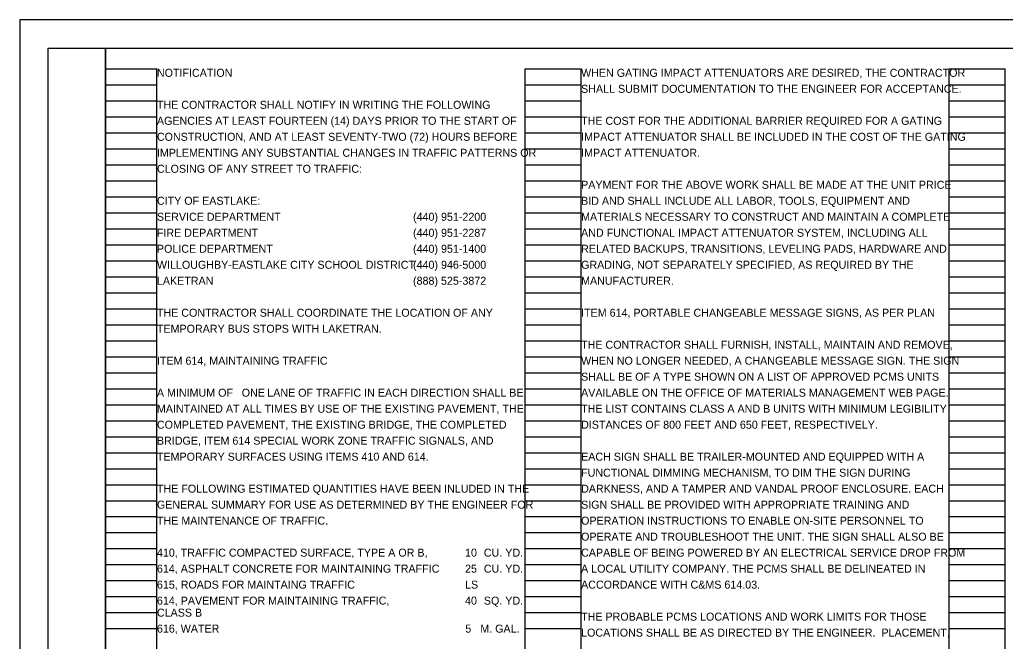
# Model space of a CAD drawing. Extents: x 0 to 34, y 0 to 22.
# Drawn here: x 0 to 17.24, y 11.12 to 22 of the extents above; entities that cross this region are included whole.
import ezdxf

# ---------------------------------------------------------------- set-up
doc = ezdxf.new("R2010")
doc.units = 0
for name, color, linetype in [('SH_Border', 7, 'Continuous'), ('SH_Cut_Line', 7, 'Continuous'), ('SH_Data', 7, 'Continuous'), ('SH_Text', 7, 'Continuous')]:
    doc.layers.add(name, color=color, linetype=linetype)

msp = doc.modelspace()

# ---------------------------------------------------------------- linework, layer by layer
at = {"layer": 'SH_Border'}
for points in [[(0.5, 21.5), (1.5, 21.5), (1.5, 0.5), (0.5, 0.5)], [(1.5, 21.5), (33.5, 21.5), (33.5, 0.5), (1.5, 0.5)]]:
    msp.add_lwpolyline(points, close=True, dxfattribs=at)
at = {"layer": 'SH_Cut_Line'}
msp.add_lwpolyline([(0, 0), (34, 0), (34, 22), (0, 22)], close=True, dxfattribs=at)
at = {"layer": 'SH_Data'}
for p, q in [((1.5, 0.98), (1.5, 21.14)), ((1.5, 21.14), (2.4, 21.14)), ((2.4, 0.98), (2.4, 21.14)), ((8.84, 0.98), (8.84, 21.14)), ((8.84, 21.14), (9.82, 21.14)), ((9.82, 0.98), (9.82, 21.14)), ((16.26, 0.98), (16.26, 21.14)), ((16.26, 21.14), (17.24, 21.14)), ((17.24, 0.98), (17.24, 21.14)), ((1.5, 20.86), (2.4, 20.86)), ((8.84, 20.86), (9.82, 20.86)), ((16.26, 20.86), (17.24, 20.86)), ((1.5, 20.58), (2.4, 20.58)), ((8.84, 20.58), (9.82, 20.58)), ((16.26, 20.58), (17.24, 20.58)), ((1.5, 20.3), (2.4, 20.3)), ((8.84, 20.3), (9.82, 20.3)), ((16.26, 20.3), (17.24, 20.3)), ((1.5, 20.02), (2.4, 20.02)), ((8.84, 20.02), (9.82, 20.02)), ((16.26, 20.02), (17.24, 20.02)), ((1.5, 19.74), (2.4, 19.74)), ((8.84, 19.74), (9.82, 19.74)), ((16.26, 19.74), (17.24, 19.74)), ((1.5, 19.46), (2.4, 19.46)), ((8.84, 19.46), (9.82, 19.46)), ((16.26, 19.46), (17.24, 19.46)), ((1.5, 19.18), (2.4, 19.18)), ((8.84, 19.18), (9.82, 19.18)), ((16.26, 19.18), (17.24, 19.18)), ((1.5, 18.9), (2.4, 18.9)), ((8.84, 18.9), (9.82, 18.9)), ((16.26, 18.9), (17.24, 18.9)), ((1.5, 18.62), (2.4, 18.62)), ((8.84, 18.62), (9.82, 18.62)), ((16.26, 18.62), (17.24, 18.62)), ((1.5, 18.34), (2.4, 18.34)), ((8.84, 18.34), (9.82, 18.34)), ((16.26, 18.34), (17.24, 18.34)), ((1.5, 18.06), (2.4, 18.06)), ((8.84, 18.06), (9.82, 18.06)), ((16.26, 18.06), (17.24, 18.06)), ((1.5, 17.78), (2.4, 17.78)), ((8.84, 17.78), (9.82, 17.78)), ((16.26, 17.78), (17.24, 17.78)), ((1.5, 17.5), (2.4, 17.5)), ((8.84, 17.5), (9.82, 17.5)), ((16.26, 17.5), (17.24, 17.5)), ((1.5, 17.22), (2.4, 17.22)), ((8.84, 17.22), (9.82, 17.22)), ((16.26, 17.22), (17.24, 17.22)), ((1.5, 16.94), (2.4, 16.94)), ((8.84, 16.94), (9.82, 16.94)), ((16.26, 16.94), (17.24, 16.94)), ((1.5, 16.66), (2.4, 16.66)), ((8.84, 16.66), (9.82, 16.66)), ((16.26, 16.66), (17.24, 16.66)), ((1.5, 16.38), (2.4, 16.38)), ((8.84, 16.38), (9.82, 16.38)), ((16.26, 16.38), (17.24, 16.38)), ((1.5, 16.1), (2.4, 16.1)), ((8.84, 16.1), (9.82, 16.1)), ((16.26, 16.1), (17.24, 16.1)), ((1.5, 15.82), (2.4, 15.82)), ((8.84, 15.82), (9.82, 15.82)), ((16.26, 15.82), (17.24, 15.82)), ((1.5, 15.54), (2.4, 15.54)), ((8.84, 15.54), (9.82, 15.54)), ((16.26, 15.54), (17.24, 15.54)), ((1.5, 15.26), (2.4, 15.26)), ((8.84, 15.26), (9.82, 15.26)), ((16.26, 15.26), (17.24, 15.26)), ((1.5, 14.98), (2.4, 14.98)), ((8.84, 14.98), (9.82, 14.98)), ((16.26, 14.98), (17.24, 14.98)), ((1.5, 14.7), (2.4, 14.7)), ((8.84, 14.7), (9.82, 14.7)), ((16.26, 14.7), (17.24, 14.7)), ((1.5, 14.42), (2.4, 14.42)), ((8.84, 14.42), (9.82, 14.42)), ((16.26, 14.42), (17.24, 14.42)), ((1.5, 14.14), (2.4, 14.14)), ((8.84, 14.14), (9.82, 14.14)), ((16.26, 14.14), (17.24, 14.14)), ((1.5, 13.86), (2.4, 13.86)), ((8.84, 13.86), (9.82, 13.86)), ((16.26, 13.86), (17.24, 13.86)), ((1.5, 13.58), (2.4, 13.58)), ((8.84, 13.58), (9.82, 13.58)), ((16.26, 13.58), (17.24, 13.58)), ((1.5, 13.3), (2.4, 13.3)), ((8.84, 13.3), (9.82, 13.3)), ((16.26, 13.3), (17.24, 13.3)), ((1.5, 13.02), (2.4, 13.02)), ((8.84, 13.02), (9.82, 13.02)), ((16.26, 13.02), (17.24, 13.02)), ((1.5, 12.74), (2.4, 12.74)), ((8.84, 12.74), (9.82, 12.74)), ((16.26, 12.74), (17.24, 12.74)), ((1.5, 12.46), (2.4, 12.46)), ((8.84, 12.46), (9.82, 12.46)), ((16.26, 12.46), (17.24, 12.46)), ((1.5, 12.18), (2.4, 12.18)), ((8.84, 12.18), (9.82, 12.18)), ((16.26, 12.18), (17.24, 12.18)), ((1.5, 11.9), (2.4, 11.9)), ((8.84, 11.9), (9.82, 11.9)), ((16.26, 11.9), (17.24, 11.9)), ((1.5, 11.62), (2.4, 11.62)), ((8.84, 11.62), (9.82, 11.62)), ((16.26, 11.62), (17.24, 11.62)), ((1.5, 11.34), (2.4, 11.34)), ((8.84, 11.34), (9.82, 11.34)), ((16.26, 11.34), (17.24, 11.34))]:
    msp.add_line(p, q, dxfattribs=at)

# ---------------------------------------------------------------- texts
at = {"layer": 'SH_Text'}
for s, p in [('NOTIFICATION', (2.4, 21)), ('WHEN GATING IMPACT ATTENUATORS ARE DESIRED, THE CONTRACTOR ', (9.82, 21)), ('SHALL SUBMIT DOCUMENTATION TO THE ENGINEER FOR ACCEPTANCE.', (9.82, 20.72)), ('THE CONTRACTOR SHALL NOTIFY IN WRITING THE FOLLOWING ', (2.4, 20.44)), ('AGENCIES AT LEAST FOURTEEN (14) DAYS PRIOR TO THE START OF ', (2.4, 20.16)), ('THE COST FOR THE ADDITIONAL BARRIER REQUIRED FOR A GATING ', (9.82, 20.16)), ('CONSTRUCTION, AND AT LEAST SEVENTY-TWO (72) HOURS BEFORE ', (2.4, 19.88)), ('IMPACT ATTENUATOR SHALL BE INCLUDED IN THE COST OF THE GATING ', (9.82, 19.88)), ('IMPLEMENTING ANY SUBSTANTIAL CHANGES IN TRAFFIC PATTERNS OR ', (2.4, 19.6)), ('IMPACT ATTENUATOR.', (9.82, 19.6)), ('CLOSING OF ANY STREET TO TRAFFIC:', (2.4, 19.32)), ('PAYMENT FOR THE ABOVE WORK SHALL BE MADE AT THE UNIT PRICE ', (9.82, 19.04)), ('CITY OF EASTLAKE:', (2.4, 18.76)), ('BID AND SHALL INCLUDE ALL LABOR, TOOLS, EQUIPMENT AND ', (9.82, 18.76)), ('SERVICE DEPARTMENT', (2.4, 18.48)), ('(440) 951-2200', (6.88, 18.48)), ('MATERIALS NECESSARY TO CONSTRUCT AND MAINTAIN A COMPLETE ', (9.82, 18.48)), ('FIRE DEPARTMENT', (2.4, 18.2)), ('(440) 951-2287', (6.88, 18.2)), ('AND FUNCTIONAL IMPACT ATTENUATOR SYSTEM, INCLUDING ALL ', (9.82, 18.2)), ('POLICE DEPARTMENT', (2.4, 17.92)), ('(440) 951-1400', (6.88, 17.92)), ('RELATED BACKUPS, TRANSITIONS, LEVELING PADS, HARDWARE AND ', (9.82, 17.92)), ('WILLOUGHBY-EASTLAKE CITY SCHOOL DISTRICT', (2.4, 17.64)), ('(440) 946-5000', (6.88, 17.64)), ('GRADING, NOT SEPARATELY SPECIFIED, AS REQUIRED BY THE ', (9.82, 17.64)), ('LAKETRAN', (2.4, 17.36)), ('(888) 525-3872', (6.88, 17.36)), ('MANUFACTURER.', (9.82, 17.36)), ('THE CONTRACTOR SHALL COORDINATE THE LOCATION OF ANY ', (2.4, 16.8)), ('ITEM 614, PORTABLE CHANGEABLE MESSAGE SIGNS, AS PER PLAN', (9.82, 16.8)), ('TEMPORARY BUS STOPS WITH LAKETRAN.', (2.4, 16.52)), ('THE CONTRACTOR SHALL FURNISH, INSTALL, MAINTAIN AND REMOVE, ', (9.82, 16.24)), ('ITEM 614, MAINTAINING TRAFFIC', (2.4, 15.96)), ('WHEN NO LONGER NEEDED, A CHANGEABLE MESSAGE SIGN. THE SIGN ', (9.82, 15.96)), ('SHALL BE OF A TYPE SHOWN ON A LIST OF APPROVED PCMS UNITS ', (9.82, 15.68)), ('A MINIMUM OF ', (2.4, 15.4)), ('ONE', (3.884, 15.4)), (' LANE OF TRAFFIC IN EACH DIRECTION SHALL BE ', (4.278, 15.4)), ('AVAILABLE ON THE OFFICE OF MATERIALS MANAGEMENT WEB PAGE. ', (9.82, 15.4)), ('MAINTAINED AT ALL TIMES BY USE OF THE EXISTING PAVEMENT, THE ', (2.4, 15.12)), ('THE LIST CONTAINS CLASS A AND B UNITS WITH MINIMUM LEGIBILITY ', (9.82, 15.12)), ('COMPLETED PAVEMENT, THE EXISTING BRIDGE, THE COMPLETED ', (2.4, 14.84)), ('DISTANCES OF 800 FEET AND 650 FEET, RESPECTIVELY.', (9.82, 14.84)), ('BRIDGE, ITEM 614 SPECIAL WORK ZONE TRAFFIC SIGNALS, AND ', (2.4, 14.56)), ('TEMPORARY SURFACES USING ITEMS 410 AND 614.', (2.4, 14.28)), ('EACH SIGN SHALL BE TRAILER-MOUNTED AND EQUIPPED WITH A ', (9.82, 14.28)), ('FUNCTIONAL DIMMING MECHANISM, TO DIM THE SIGN DURING ', (9.82, 14)), ('THE FOLLOWING ESTIMATED QUANTITIES HAVE BEEN INLUDED IN THE', (2.4, 13.72)), ('DARKNESS, AND A TAMPER AND VANDAL PROOF ENCLOSURE. EACH ', (9.82, 13.72)), ('GENERAL SUMMARY FOR USE AS DETERMINED BY THE ENGINEER FOR ', (2.4, 13.44)), ('SIGN SHALL BE PROVIDED WITH APPROPRIATE TRAINING AND ', (9.82, 13.44)), ('THE MAINTENANCE OF TRAFFIC.', (2.4, 13.16)), ('OPERATION INSTRUCTIONS TO ENABLE ON-SITE PERSONNEL TO ', (9.82, 13.16)), ('OPERATE AND TROUBLESHOOT THE UNIT. THE SIGN SHALL ALSO BE ', (9.82, 12.88)), ('410, TRAFFIC COMPACTED SURFACE, TYPE A OR B, ', (2.4, 12.6)), (' 10 ', (7.738, 12.6)), (' CU. YD.', (8.067, 12.6)), ('CAPABLE OF BEING POWERED BY AN ELECTRICAL SERVICE DROP FROM ', (9.82, 12.6)), ('614, ASPHALT CONCRETE FOR MAINTAINING TRAFFIC', (2.4, 12.32)), (' 25 ', (7.738, 12.32)), (' CU. YD.', (8.067, 12.32)), ('A LOCAL UTILITY COMPANY. THE PCMS SHALL BE DELINEATED IN ', (9.82, 12.32)), ('615, ROADS FOR MAINTAING TRAFFIC', (2.4, 12.04)), (' LS ', (7.738, 12.04)), ('ACCORDANCE WITH C&MS 614.03.', (9.82, 12.04)), ('614, PAVEMENT FOR MAINTAINING TRAFFIC, ', (2.4, 11.76)), (' 40', (7.738, 11.76)), (' SQ. YD.', (8.067, 11.76)), ('CLASS B', (2.4, 11.55)), ('THE PROBABLE PCMS LOCATIONS AND WORK LIMITS FOR THOSE ', (9.82, 11.48)), ('616, WATER', (2.4, 11.27)), ('  5  ', (7.691, 11.27)), (' M. GAL.', (8.005, 11.27)), ('LOCATIONS SHALL BE AS DIRECTED BY THE ENGINEER.  PLACEMENT, ', (9.82, 11.2))]:
    msp.add_text(s, height=0.14, dxfattribs=at).set_placement(p)

doc.saveas('drawing.dxf')
